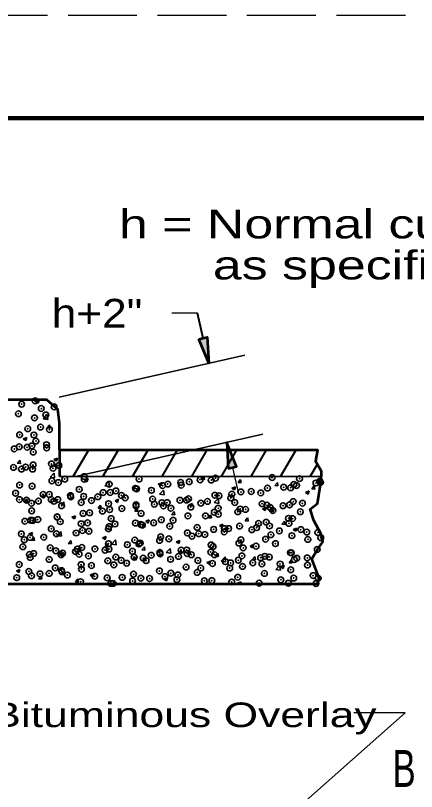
# Model space of a CAD drawing. Extents: x 14 to 49.3, y 28 to 50.
# Drawn here: x 22.425 to 24.379, y 46.258 to 50.044 of the extents above; entities that cross this region are included whole.
import ezdxf

# ---------------------------------------------------------------- set-up
doc = ezdxf.new("R2010")
doc.units = 0
doc.header["$LTSCALE"] = 0.056
doc.header["$PDMODE"] = 32
doc.header["$PDSIZE"] = 0.028
doc.linetypes.add('LONG_DASHED', pattern=[7.5, 6, -1.5])
for name, color, linetype, lineweight in [('1', 7, 'Continuous', 35), ('3', 7, 'Continuous', 13), ('5', 7, 'Continuous', 35), ('6', 7, 'Continuous', 13)]:
    doc.layers.add(name, color=color, linetype=linetype, lineweight=lineweight)

msp = doc.modelspace()

# ---------------------------------------------------------------- hatches: boundary and pattern name
at = {"layer": '1'}
for points in [[(23.31867, 48.46508), (23.35925, 48.47433), (23.36667, 48.34775), (23.36667, 48.34775)], [(23.46167, 47.83467), (23.50233, 47.84392), (23.45433, 47.96117), (23.45433, 47.96117)]]:
    msp.add_hatch(color=256, dxfattribs=at).paths.add_polyline_path(points)

# ---------------------------------------------------------------- linework, layer by layer
at = {"layer": '1', "linetype": 'LONG_DASHED', "lineweight": 25}
msp.add_line((49.17658, 50.04392), (13.97658, 50.04392), dxfattribs=at)
at = {"layer": '1', "lineweight": 158}
msp.add_line((49.09325, 49.54392), (16.59325, 49.54392), dxfattribs=at)
at = {"layer": '1', "lineweight": 25}
for p, q in [((23.31133, 48.59158), (23.18633, 48.59158)), ((23.482, 47.83925), (23.50967, 47.71733))]:
    msp.add_line(p, q, dxfattribs=at)
at = {"layer": '1', "lineweight": 40}
for p, q in [((23.339, 48.46967), (23.31133, 48.59158)), ((22.70633, 47.79467), (22.78192, 47.92558)), ((22.85067, 47.79467), (22.92625, 47.92558)), ((22.995, 47.79467), (23.07058, 47.92558)), ((23.13933, 47.79467), (23.21492, 47.92558)), ((23.28367, 47.79467), (23.35925, 47.92558)), ((23.428, 47.79467), (23.50358, 47.92558)), ((23.57233, 47.79467), (23.64792, 47.92558)), ((23.71667, 47.79467), (23.79225, 47.92558)), ((23.861, 47.79467), (23.89567, 47.85467))]:
    msp.add_line(p, q, dxfattribs=at)
at = {"layer": '1'}
for p, q in [((22.63817, 48.1825), (23.54217, 48.38758)), ((22.523, 48.16033), (22.5405, 48.16708)), ((22.523, 48.16033), (22.53542, 48.152)), ((22.53542, 48.152), (22.5405, 48.16708)), ((22.55975, 48.07642), (22.57925, 48.09675)), ((22.55975, 48.07642), (22.582, 48.073)), ((22.582, 48.073), (22.57925, 48.09675)), ((22.578, 48.03292), (22.59008, 48.04725)), ((22.593, 48.03158), (22.59008, 48.04725)), ((22.578, 48.03292), (22.593, 48.03158)), ((22.72592, 47.79592), (23.62992, 48.001)), ((22.46217, 47.97908), (22.47967, 47.98575)), ((22.46217, 47.97908), (22.47458, 47.97067)), ((22.47458, 47.97067), (22.47967, 47.98575)), ((22.43342, 47.86058), (22.44542, 47.87492)), ((22.43342, 47.86058), (22.44833, 47.85925)), ((22.44833, 47.85925), (22.4455, 47.87492)), ((22.61133, 47.87842), (22.62892, 47.88517)), ((22.61133, 47.87842), (22.62383, 47.87)), ((22.61275, 47.84483), (22.62475, 47.85925)), ((22.62383, 47.87), (22.62892, 47.88508)), ((22.62767, 47.8435), (22.62475, 47.85925)), ((22.59292, 47.7915), (22.61233, 47.81183)), ((22.61517, 47.78808), (22.61242, 47.81183)), ((22.61275, 47.84483), (22.62767, 47.84358)), ((22.59292, 47.7915), (22.61517, 47.78808)), ((23.914, 47.79467), (22.63958, 47.79467)), ((22.76058, 47.77775), (22.77808, 47.7845)), ((22.76058, 47.77775), (22.773, 47.76933)), ((22.77308, 47.76933), (22.77808, 47.7845)), ((23.33, 47.78208), (23.3405, 47.79467)), ((23.33, 47.78208), (23.34492, 47.78083)), ((23.34492, 47.78075), (23.34242, 47.79467)), ((23.50933, 47.76642), (23.52133, 47.78075)), ((23.52425, 47.76508), (23.52133, 47.78075)), ((22.85967, 47.75017), (22.87917, 47.77042)), ((22.85967, 47.75017), (22.88192, 47.74667)), ((22.882, 47.74667), (22.87917, 47.77042)), ((23.11992, 47.75775), (23.13742, 47.76442)), ((23.11992, 47.75775), (23.13233, 47.74933)), ((23.13233, 47.74933), (23.13742, 47.76442)), ((23.47917, 47.73775), (23.49667, 47.74442)), ((23.47917, 47.73775), (23.49158, 47.72933)), ((23.49158, 47.72933), (23.49667, 47.74442)), ((23.50933, 47.76642), (23.52425, 47.76508)), ((23.68858, 47.75075), (23.70067, 47.76508)), ((23.68858, 47.75075), (23.70358, 47.74942)), ((23.70358, 47.74942), (23.70067, 47.76508)), ((23.86792, 47.735), (23.88, 47.74942)), ((23.88292, 47.73375), (23.88, 47.74942)), ((22.55058, 47.69708), (22.56808, 47.70383)), ((22.563, 47.68875), (22.56808, 47.70383)), ((23.1265, 47.70875), (23.146, 47.72908)), ((23.1265, 47.70875), (23.14875, 47.70533)), ((23.14875, 47.70533), (23.146, 47.72908)), ((23.83842, 47.71767), (23.85592, 47.72442)), ((23.83842, 47.71767), (23.85092, 47.70933)), ((23.85092, 47.70933), (23.856, 47.72442)), ((23.86792, 47.735), (23.88283, 47.73375)), ((22.46808, 47.6725), (22.48017, 47.68683)), ((22.46808, 47.6725), (22.483, 47.67117)), ((22.46808, 47.6725), (22.483, 47.67117)), ((22.48308, 47.67117), (22.48017, 47.68683)), ((22.55058, 47.69708), (22.563, 47.68875)), ((22.64742, 47.65683), (22.6595, 47.67117)), ((22.66233, 47.6555), (22.6595, 47.67117)), ((22.90983, 47.67708), (22.92733, 47.68383)), ((22.90983, 47.67708), (22.92225, 47.66875)), ((22.92225, 47.66867), (22.92733, 47.68383)), ((23.26908, 47.65708), (23.28658, 47.66383)), ((23.28158, 47.64867), (23.28667, 47.66375)), ((23.28158, 47.64867), (23.28667, 47.66375)), ((23.39333, 47.66742), (23.41283, 47.68767)), ((23.39333, 47.66742), (23.41558, 47.66392)), ((23.41558, 47.66392), (23.41283, 47.68767)), ((22.64742, 47.65683), (22.66233, 47.6555)), ((22.82675, 47.64108), (22.83875, 47.6555)), ((22.82675, 47.64108), (22.84167, 47.63983)), ((22.84167, 47.63983), (22.83875, 47.6555)), ((23.006, 47.62542), (23.01808, 47.63983)), ((23.006, 47.62542), (23.021, 47.62408)), ((23.021, 47.62408), (23.01808, 47.63975)), ((23.18533, 47.60975), (23.19742, 47.62408)), ((23.20033, 47.60842), (23.19742, 47.62408)), ((23.26908, 47.65708), (23.28158, 47.64867)), ((23.62842, 47.63708), (23.64592, 47.64375)), ((23.62842, 47.63708), (23.64592, 47.64375)), ((23.62842, 47.63708), (23.64083, 47.62867)), ((23.64083, 47.62867), (23.64592, 47.64375)), ((23.66017, 47.626), (23.67958, 47.64633)), ((23.66017, 47.626), (23.68233, 47.62258)), ((23.68242, 47.62258), (23.67967, 47.64633)), ((22.69975, 47.5965), (22.71725, 47.60317)), ((22.69975, 47.5965), (22.71217, 47.58808)), ((22.71225, 47.58808), (22.71725, 47.60317)), ((23.18533, 47.60975), (23.20033, 47.60842)), ((23.36467, 47.59408), (23.37675, 47.60842)), ((23.36467, 47.59408), (23.37958, 47.59275)), ((23.37967, 47.59275), (23.37675, 47.60842)), ((23.544, 47.57833), (23.556, 47.59275)), ((23.55892, 47.57708), (23.55608, 47.59275)), ((23.05908, 47.57642), (23.07658, 47.58317)), ((23.05908, 47.57642), (23.0715, 47.56808)), ((23.0715, 47.56808), (23.07658, 47.58317)), ((23.41833, 47.55642), (23.43583, 47.56317)), ((23.41833, 47.55642), (23.43075, 47.548)), ((23.43075, 47.548), (23.43583, 47.56317)), ((23.544, 47.57833), (23.55892, 47.57708)), ((23.72333, 47.56267), (23.73533, 47.577)), ((23.72333, 47.56267), (23.73825, 47.56133)), ((23.73825, 47.56133), (23.73533, 47.577)), ((22.48975, 47.51583), (22.50725, 47.52258)), ((22.48975, 47.51583), (22.50217, 47.50742)), ((22.50217, 47.50742), (22.50725, 47.52258)), ((22.62608, 47.50658), (22.6455, 47.52692)), ((22.64833, 47.50317), (22.6455, 47.52692)), ((23.77758, 47.53642), (23.79508, 47.54308)), ((23.77758, 47.53642), (23.79008, 47.528)), ((23.79008, 47.528), (23.79517, 47.54308)), ((22.50275, 47.48442), (22.51483, 47.49883)), ((22.50275, 47.48442), (22.51775, 47.48317)), ((22.51775, 47.48317), (22.51483, 47.49883)), ((22.62608, 47.50658), (22.64825, 47.50317)), ((22.68208, 47.46875), (22.69417, 47.48308)), ((22.69708, 47.46742), (22.69417, 47.48308)), ((22.849, 47.49583), (22.8665, 47.5025)), ((22.849, 47.49583), (22.86142, 47.48742)), ((22.86142, 47.48742), (22.8665, 47.5025)), ((22.89283, 47.46525), (22.91233, 47.4855)), ((22.91508, 47.46175), (22.91233, 47.4855)), ((23.20825, 47.47575), (23.22575, 47.4825)), ((23.20825, 47.47575), (23.22075, 47.46742)), ((23.22075, 47.46742), (23.22583, 47.4825)), ((22.68208, 47.46875), (22.697, 47.46742)), ((22.86142, 47.45308), (22.8735, 47.46742)), ((22.86142, 47.45308), (22.87633, 47.45175)), ((22.87633, 47.45175), (22.8735, 47.46742)), ((22.89283, 47.46525), (22.91508, 47.46183)), ((23.04075, 47.43742), (23.05275, 47.45175)), ((23.04075, 47.43742), (23.05567, 47.43608)), ((23.05567, 47.43608), (23.05283, 47.45175)), ((23.15967, 47.42383), (23.17917, 47.44417)), ((23.18192, 47.42042), (23.17917, 47.44417)), ((23.22, 47.42167), (23.23208, 47.43608)), ((23.235, 47.42042), (23.23208, 47.43608)), ((23.56758, 47.45575), (23.58508, 47.4625)), ((23.56758, 47.45575), (23.58, 47.44742)), ((23.58, 47.44733), (23.58508, 47.4625)), ((22.63892, 47.41517), (22.65642, 47.42192)), ((22.63892, 47.41517), (22.65142, 47.40683)), ((22.65142, 47.40675), (22.6565, 47.42192)), ((22.99825, 47.39517), (23.01575, 47.40192)), ((22.99825, 47.39517), (23.01067, 47.38675)), ((23.01067, 47.38675), (23.01575, 47.40183)), ((23.15967, 47.42383), (23.18192, 47.42042)), ((23.22, 47.42167), (23.235, 47.42042)), ((23.39933, 47.406), (23.41142, 47.42033)), ((23.39933, 47.406), (23.41433, 47.40467)), ((23.41433, 47.40467), (23.41142, 47.42033)), ((23.4265, 47.3825), (23.44592, 47.40275)), ((23.44875, 47.379), (23.446, 47.40275)), ((23.57867, 47.39033), (23.59075, 47.40467)), ((23.59367, 47.389), (23.59075, 47.40467)), ((23.3575, 47.37517), (23.375, 47.38183)), ((23.3575, 47.37517), (23.36992, 47.36675)), ((23.36992, 47.36675), (23.375, 47.38183)), ((23.4265, 47.3825), (23.44867, 47.379)), ((23.57867, 47.39033), (23.59358, 47.389)), ((23.69325, 47.34108), (23.71275, 47.36142)), ((23.7155, 47.33767), (23.71275, 47.36142)), ((23.71675, 47.35508), (23.73433, 47.36183)), ((23.72925, 47.34675), (23.73433, 47.36183)), ((23.758, 47.37467), (23.77, 47.389)), ((23.758, 47.37467), (23.77292, 47.37333)), ((23.77292, 47.37333), (23.77008, 47.389)), ((22.42892, 47.33458), (22.44642, 47.34125)), ((22.42892, 47.33458), (22.44133, 47.32617)), ((22.44133, 47.32617), (22.44642, 47.34125)), ((22.78817, 47.3145), (22.80567, 47.32125)), ((22.80058, 47.30617), (22.80567, 47.32125)), ((23.69325, 47.34108), (23.7155, 47.33767)), ((23.71675, 47.35508), (23.72925, 47.34675)), ((22.5375, 47.29642), (22.5495, 47.31075)), ((22.5375, 47.29642), (22.55242, 47.29508)), ((22.55242, 47.29508), (22.5495, 47.31075)), ((22.71675, 47.28075), (22.72883, 47.29508)), ((22.73175, 47.27942), (22.72883, 47.29508)), ((22.78817, 47.3145), (22.80058, 47.30617)), ((23.14742, 47.2945), (23.16492, 47.30125)), ((23.14742, 47.2945), (23.15992, 47.28608)), ((23.15992, 47.28608), (23.165, 47.30125)), ((23.50675, 47.2745), (23.52425, 47.28117)), ((23.52083, 47.271), (23.52425, 47.28117)), ((22.71675, 47.28075), (22.73175, 47.27942)), ((22.90117, 47.271), (22.90817, 47.27942)), ((22.90967, 47.271), (22.90817, 47.27942)), ((23.50675, 47.2745), (23.51183, 47.271))]:
    msp.add_line(p, q, dxfattribs=at)
at = {"layer": '1', "lineweight": 53}
msp.add_line((22.63958, 47.92558), (22.63958, 47.79467), dxfattribs=at)
for points in [[(23.31867, 48.46508), (23.35925, 48.47433), (23.36667, 48.34775), (23.36667, 48.34775)], [(23.46167, 47.83467), (23.50233, 47.84392), (23.45433, 47.96117), (23.45433, 47.96117)]]:
    msp.add_lwpolyline(points, close=True, dxfattribs=at)
for points in [[(22.63958, 47.92558), (22.63958, 48.05642), (22.63067, 48.12192), (22.57725, 48.16867), (20.43842, 48.16867), (20.39383, 48.11258), (20.38492, 48.02842)], [(22.63958, 47.92558), (23.89617, 47.92558), (23.88725, 47.86942), (23.914, 47.82267), (23.914, 47.79467)], [(18.87883, 47.271), (23.89617, 47.271), (23.90508, 47.29908), (23.88725, 47.34583), (23.86942, 47.39258), (23.89617, 47.43933), (23.92292, 47.47675), (23.914, 47.51417), (23.87833, 47.57958), (23.8605, 47.63567), (23.89617, 47.66375), (23.914, 47.77592), (23.914, 47.79467)]]:
    msp.add_lwpolyline(points, dxfattribs=at)
at = {"layer": '1'}
for p in [(22.45475, 48.148), (22.52042, 48.16392), (22.43908, 48.10125), (22.55025, 48.12675), (22.61283, 48.135), (22.51733, 48.08067), (22.57258, 48.09567), (22.4845, 48.02808), (22.54708, 48.03633), (22.44442, 47.99883), (22.51433, 47.9975), (22.59017, 48.02392), (22.52383, 47.96792), (22.576, 47.95025), (22.41875, 47.9295), (22.44317, 47.94), (22.48133, 47.93775), (22.50433, 47.944), (22.51133, 47.91425), (22.57658, 47.93433), (22.41558, 47.83917), (22.47417, 47.84083), (22.51025, 47.85158), (22.59975, 47.8565), (22.60758, 47.83517), (22.63658, 47.84858), (22.454, 47.83142), (22.50825, 47.831), (22.60233, 47.77383), (22.63358, 47.76542), (22.66492, 47.78208), (22.75967, 47.7945), (22.75983, 47.78142), (23.02683, 47.78242), (23.2295, 47.76642), (23.27117, 47.76925), (23.32417, 47.77892), (23.37833, 47.77758), (23.3995, 47.78692), (23.67525, 47.79008), (23.80867, 47.78442), (23.88875, 47.76325), (23.90725, 47.772), (23.91125, 47.76517), (22.4445, 47.753), (22.50525, 47.74783), (22.73525, 47.73233), (22.88108, 47.75733), (22.91433, 47.72492), (23.009, 47.73742), (23.015, 47.7345), (23.08675, 47.7275), (23.14133, 47.7505), (23.16692, 47.75817), (23.23258, 47.7525), (23.57358, 47.72175), (23.65258, 47.73842), (23.73142, 47.74258), (23.76542, 47.74008), (23.78092, 47.756), (23.794, 47.75083), (22.42542, 47.71308), (22.55892, 47.70742), (22.5895, 47.70733), (22.59917, 47.68342), (22.69233, 47.70183), (22.69383, 47.69592), (22.75683, 47.69817), (22.82583, 47.69617), (22.85175, 47.71667), (22.88667, 47.71692), (22.94092, 47.7025), (22.95925, 47.6905), (23.09275, 47.68492), (23.26808, 47.68608), (23.3965, 47.70367), (23.41633, 47.70108), (23.47383, 47.69008), (23.47892, 47.70933), (23.52275, 47.71967), (23.61958, 47.71508), (22.44367, 47.68225), (22.47817, 47.6795), (22.50217, 47.66458), (22.53658, 47.67517), (22.61158, 47.67383), (22.6305, 47.68217), (22.64933, 47.65242), (22.74508, 47.66825), (22.79517, 47.67742), (22.8785, 47.66258), (23.012, 47.65692), (23.012, 47.65133), (23.10117, 47.65958), (23.13825, 47.66733), (23.14542, 47.65133), (23.16375, 47.66783), (23.22617, 47.67925), (23.25842, 47.68025), (23.27892, 47.64567), (23.328, 47.665), (23.35967, 47.67358), (23.49308, 47.668), (23.62658, 47.66233), (23.64958, 47.65517), (23.72825, 47.65217), (23.76, 47.65667), (23.77792, 47.67275), (23.82292, 47.66467), (22.50358, 47.62742), (22.75375, 47.61492), (22.786, 47.61808), (22.84858, 47.62633), (22.88358, 47.63367), (22.94325, 47.63883), (23.03642, 47.615), (23.18225, 47.64), (23.39342, 47.62042), (23.41233, 47.64), (23.41308, 47.61075), (23.50783, 47.62317), (23.51967, 47.63642), (23.54583, 47.63442), (23.66567, 47.644), (23.67925, 47.62875), (23.81275, 47.62308), (22.47083, 47.57658), (22.49917, 47.58133), (22.50917, 47.58033), (22.53342, 47.58483), (22.6275, 47.59892), (22.62808, 47.59733), (22.64267, 47.57475), (22.89067, 47.58992), (23.13525, 47.58408), (23.19267, 47.58167), (23.26508, 47.60283), (23.3505, 47.6025), (23.6465, 47.57192), (23.75508, 47.59092), (23.77483, 47.58958), (22.59908, 47.53992), (22.74483, 47.56492), (22.77608, 47.56908), (22.8775, 47.54017), (22.88058, 47.5505), (22.9095, 47.56342), (23.00892, 47.56808), (23.03542, 47.561), (23.043, 47.55783), (23.098, 47.56925), (23.17642, 47.55217), (23.30992, 47.5465), (23.39042, 47.53717), (23.44333, 47.54092), (23.4635, 47.54092), (23.51667, 47.55325), (23.57683, 47.53525), (23.59992, 47.54533), (23.60933, 47.56592), (23.6625, 47.55358), (23.75717, 47.56608), (23.815, 47.53608), (22.45325, 47.51492), (22.49608, 47.49808), (22.56233, 47.49867), (22.62442, 47.51575), (22.72025, 47.5195), (22.75075, 47.53175), (22.78283, 47.52775), (23.13217, 47.50083), (23.262, 47.51958), (23.28475, 47.50383), (23.31767, 47.51583), (23.34733, 47.51208), (23.442, 47.52458), (23.66917, 47.511), (23.71025, 47.52958), (23.77183, 47.50633), (23.84375, 47.524), (23.89808, 47.52233), (23.91192, 47.4965), (22.46767, 47.48625), (22.8775, 47.46725), (22.96958, 47.46242), (23.00592, 47.48483), (23.02608, 47.46583), (23.03217, 47.47058), (23.12692, 47.48308), (23.17192, 47.49083), (23.37758, 47.461), (23.51358, 47.47), (23.52342, 47.486), (23.6435, 47.48875), (23.69142, 47.4675), (23.84933, 47.48825), (22.4605, 47.45258), (22.51317, 47.419), (22.59392, 47.447), (22.62142, 47.4325), (22.65442, 47.42092), (22.717, 47.42908), (22.72742, 47.44133), (22.74767, 47.4485), (22.81175, 47.44158), (22.86083, 47.43567), (22.88033, 47.44075), (22.99433, 47.43008), (23.12775, 47.42442), (23.23183, 47.43592), (23.259, 47.43642), (23.26125, 47.41875), (23.37625, 47.426), (23.38733, 47.454), (23.53417, 47.44675), (23.59675, 47.455), (23.76467, 47.4235), (23.76875, 47.42308), (23.89508, 47.43908), (22.49308, 47.41492), (22.49658, 47.40008), (22.58875, 47.39075), (22.64667, 47.41342), (22.7345, 47.41575), (22.78008, 47.40775), (22.8745, 47.384), (22.91358, 47.40208), (22.94025, 47.38592), (23.00283, 47.40167), (23.047, 47.3965), (23.06108, 47.3845), (23.086, 47.41092), (23.12917, 47.41767), (23.1805, 47.39083), (23.219, 47.40525), (23.28158, 47.4135), (23.31392, 47.38517), (23.39467, 47.41317), (23.51058, 47.38675), (23.52817, 47.4075), (23.61892, 47.3985), (23.64042, 47.4055), (23.66158, 47.40183), (23.7835, 47.38967), (23.79508, 47.39625), (23.84617, 47.39792), (22.44292, 47.36575), (22.61833, 47.34925), (22.74467, 47.36525), (22.74592, 47.343), (22.79442, 47.36083), (22.90383, 47.36375), (22.96642, 47.372), (23.25592, 47.35317), (23.32725, 47.3485), (23.38433, 47.37075), (23.44742, 47.37958), (23.46842, 47.34817), (23.47308, 47.3735), (23.531, 47.35642), (23.58083, 47.37392), (23.62567, 47.36883), (23.71433, 47.36825), (23.84775, 47.36267), (22.49, 47.33167), (22.50283, 47.31083), (22.54417, 47.31992), (22.58867, 47.32225), (22.64867, 47.33583), (22.65125, 47.3305), (22.67767, 47.31425), (22.81108, 47.30858), (22.99983, 47.31842), (23.12608, 47.33442), (23.15325, 47.30667), (23.1815, 47.32342), (23.21583, 47.31492), (23.3105, 47.32733), (23.63742, 47.32225), (23.76575, 47.33992), (23.875, 47.31175), (22.43083, 47.3015), (22.74158, 47.28208), (22.87142, 47.30083), (22.88992, 47.27342), (22.90067, 47.27342), (22.94458, 47.303), (22.99533, 47.28583), (23.03567, 47.29842), (23.078, 47.29733), (23.2115, 47.29167), (23.34492, 47.28608), (23.38125, 47.2875), (23.47842, 47.28042), (23.5075, 47.3035), (23.61183, 47.27475), (23.71775, 47.291), (23.75433, 47.27442), (23.78033, 47.29925), (23.889, 47.27267), (23.90017, 47.29942)]:
    msp.add_point(p, dxfattribs=at)
at = {"layer": '3', "lineweight": 25}
msp.add_lwpolyline([(23.56808, 45.97133), (24.32342, 46.6425), (24.07375, 46.6425)], dxfattribs=at)
at = {"layer": '6', "lineweight": 53}
for p, q in [((23.36667, 48.34775), (23.36675, 48.34775)), ((22.57725, 48.16867), (22.57733, 48.16867)), ((22.66492, 47.78208), (22.665, 47.78208))]:
    msp.add_line(p, q, dxfattribs=at)

# ---------------------------------------------------------------- texts
at = {"layer": '1', "width": 1.15}
msp.add_text('h+2"', height=0.14, dxfattribs=at).set_placement((22.60133, 48.52158))
at = {"layer": '3', "width": 1.35}
for s, height, p in [('h = Normal curb or median height', 0.14, (22.92883, 48.95675)), ('as specified on the Plans', 0.14, (23.38642, 48.75642)), ('Concrete Transition Pavement with 2" Bituminous Overlay', 0.12, (18.61742, 46.5725))]:
    msp.add_text(s, height=height, dxfattribs=at).set_placement(p)
at = {"layer": '5', "width": 0.7}
msp.add_text('B', height=0.18, dxfattribs=at).set_placement((24.26233, 46.28058))

doc.saveas('drawing.dxf')
